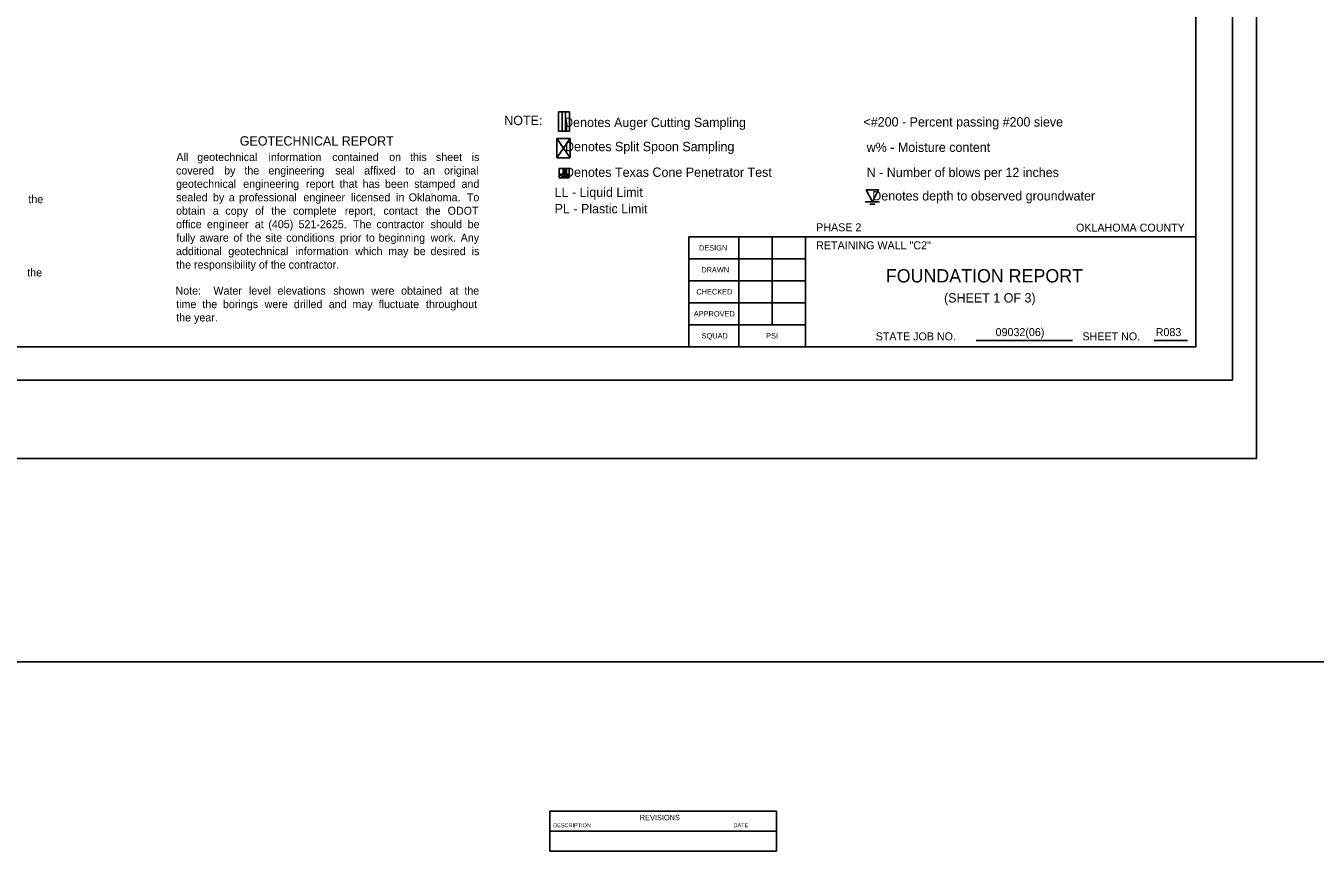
# Model space of a CAD drawing. Extents: x -2 to 138, y 24 to 58.
# Drawn here: x 24.17 to 43.5, y 24.08 to 36.46 of the extents above; entities that cross this region are included whole.
import ezdxf

# ---------------------------------------------------------------- set-up
doc = ezdxf.new("R2010")
doc.units = 0
for name, color, linetype in [('4', 7, 'Continuous'), ('REVBLK', 7, 'Continuous'), ('S', 7, 'Continuous'), ('SHT_Plot_Shape_Full', 7, 'Continuous'), ('SHT_Plot_Shape_Half', 7, 'Continuous'), ('SHT_Sheet_Border', 7, 'Continuous'), ('SHT_Standard_Sheet_Lines', 7, 'Continuous'), ('SHT_Standard_Sheet_Txt', 7, 'Continuous'), ('T', 7, 'Continuous'), ('T-5', 7, 'Continuous'), ('Text', 7, 'Continuous')]:
    doc.layers.add(name, color=color, linetype=linetype)

# ---------------------------------------------------------------- blocks, each defined once
blk = doc.blocks.new('DGRFC_WTLEV1_1')
for points in [[(-0.005, 0), (0.005, 0)], [(0, 0), (0.00417, 0.00833), (-0.00417, 0.00833), (0, 0)], [(-0.00167, -0.00167), (0.00167, -0.00167)]]:
    blk.add_lwpolyline(points)

msp = doc.modelspace()

# ---------------------------------------------------------------- linework, layer by layer
msp.add_line((32.155, 35.172), (32.155, 34.881))
for points in [[(32.155, 35.172), (32.322, 35.172)], [(32.322, 34.881), (32.322, 35.172)], [(32.155, 34.881), (32.322, 34.881)], [(32.155, 34.881), (32.322, 34.881)]]:
    msp.add_lwpolyline(points)
for points in [[(32.213, 35.172), (32.213, 34.881), (32.263, 34.881), (32.263, 35.172)], [(32.278, 35.005), (32.272, 35.047), (32.263, 35.087), (32.278, 35.005)], [(32.263, 35.087), (32.263, 34.881), (32.278, 35.005), (32.263, 35.087)], [(32.263, 34.881), (32.278, 34.922), (32.278, 35.005), (32.263, 34.881)], [(32.278, 34.922), (32.28, 34.963), (32.278, 35.005), (32.278, 34.922)], [(32.263, 34.881), (32.272, 34.881), (32.278, 34.922), (32.263, 34.881)]]:
    msp.add_lwpolyline(points, close=True)
at = {"layer": 'REVBLK'}
for p, q in [((32.025, 24.676), (35.425, 24.676)), ((32.025, 24.676), (32.025, 24.076)), ((35.425, 24.676), (35.425, 24.076)), ((32.025, 24.376), (35.425, 24.376)), ((32.025, 24.076), (35.425, 24.076))]:
    msp.add_line(p, q, dxfattribs=at)
at = {"layer": 'S'}
msp.add_lwpolyline([(-2.212, 26.92), (137.529, 26.92), (137.529, 58.049), (-2.212, 58.049)], close=True, dxfattribs=at)
at = {"layer": 'SHT_Plot_Shape_Full'}
msp.add_lwpolyline([(6.624, 53.971), (42.624, 53.971), (42.624, 29.971), (6.624, 29.971)], close=True, dxfattribs=at)
at = {"layer": 'SHT_Plot_Shape_Half'}
msp.add_lwpolyline([(8.262, 53.146), (42.262, 53.146), (42.262, 31.146), (8.262, 31.146)], close=True, dxfattribs=at)
at = {"layer": 'SHT_Sheet_Border'}
for p, q in [((34.112, 31.646), (34.112, 33.296)), ((34.112, 33.296), (41.712, 33.296)), ((35.862, 31.646), (35.862, 33.297))]:
    msp.add_line(p, q, dxfattribs=at)
msp.add_lwpolyline([(10.212, 52.646), (41.712, 52.646), (41.712, 31.646), (10.212, 31.646)], close=True, dxfattribs=at)
at = {"layer": 'SHT_Standard_Sheet_Lines'}
for p, q in [((34.862, 31.646), (34.862, 33.297)), ((35.362, 31.976), (35.362, 33.297)), ((38.422, 31.742), (39.863, 31.742)), ((41.087, 31.742), (41.59, 31.742))]:
    msp.add_line(p, q, dxfattribs=at)
for points in [[(35.862, 32.966), (34.112, 32.966)], [(35.862, 32.636), (34.112, 32.636)], [(35.862, 32.306), (34.112, 32.306)], [(35.862, 31.976), (34.112, 31.976)]]:
    msp.add_lwpolyline(points, dxfattribs=at)
at = {"layer": 'Text'}
for p, q in [((32.131, 34.481), (32.131, 34.773)), ((32.167, 34.181), (32.167, 34.322))]:
    msp.add_line(p, q, dxfattribs=at)
for points in [[(32.131, 34.481), (32.331, 34.773)], [(32.131, 34.773), (32.331, 34.481)], [(32.131, 34.773), (32.331, 34.773)], [(32.331, 34.481), (32.331, 34.773)], [(32.131, 34.481), (32.331, 34.481)], [(32.167, 34.322), (32.317, 34.322)], [(32.317, 34.181), (32.317, 34.322)], [(32.167, 34.181), (32.317, 34.181)]]:
    msp.add_lwpolyline(points, dxfattribs=at)
for points in [[(32.227, 34.237), (32.167, 34.237), (32.242, 34.181), (32.227, 34.237)], [(32.227, 34.237), (32.257, 34.322), (32.227, 34.322), (32.227, 34.237)], [(32.227, 34.237), (32.257, 34.237), (32.257, 34.322), (32.227, 34.237)], [(32.227, 34.237), (32.242, 34.181), (32.257, 34.237), (32.227, 34.237)], [(32.242, 34.181), (32.317, 34.237), (32.257, 34.237), (32.242, 34.181)]]:
    msp.add_lwpolyline(points, close=True, dxfattribs=at)

# ---------------------------------------------------------------- block references
at = {"layer": 'Text', "xscale": 21.6, "yscale": 21.6}
msp.add_blockref('DGRFC_WTLEV1_1', (36.863, 33.823), dxfattribs=at)

# ---------------------------------------------------------------- texts
at = {"layer": '4'}
msp.add_text('FOUNDATION REPORT', height=0.2, dxfattribs=at).set_placement((37.065, 32.611))
at = {"layer": 'REVBLK'}
for s, height, p in [('REVISIONS', 0.08, (33.376, 24.542)), ('DESCRIPTION', 0.06, (32.077, 24.436)), ('DATE', 0.06, (34.781, 24.436))]:
    msp.add_text(s, height=height, dxfattribs=at).set_placement(p)
at = {"layer": 'SHT_Standard_Sheet_Txt'}
for s, height, p in [('DESIGN', 0.08, (34.264, 33.091)), ('DRAWN', 0.08, (34.299, 32.761)), ('CHECKED', 0.08, (34.225, 32.431)), ('APPROVED', 0.08, (34.186, 32.101)), ('SQUAD', 0.08, (34.303, 31.771)), ('PSI', 0.08, (35.27, 31.771)), ('STATE JOB NO.', 0.12, (36.913, 31.742)), ('SHEET NO. ', 0.12, (40.013, 31.742))]:
    msp.add_text(s, height=height, dxfattribs=at).set_placement(p)
at = {"layer": 'T'}
for s, p in [('PHASE 2', (36.021, 33.379)), ('OKLAHOMA COUNTY', (39.917, 33.374)), ('RETAINING WALL "C2" ', (36.021, 33.108)), ('09032(06)', (38.711, 31.806)), ('R083', (41.112, 31.806))]:
    msp.add_text(s, height=0.12, dxfattribs=at).set_placement(p)
at = {"layer": 'T-5'}
msp.add_text('(SHEET 1 OF 3)', height=0.14, dxfattribs=at).set_placement((37.938, 32.31))
at = {"layer": 'Text'}
for s, height, p in [('NOTE:', 0.14, (31.344, 34.972)), ('    Denotes Auger Cutting Sampling', 0.14, (32.033, 34.943)), (' <#200 - Percent passing #200 sieve', 0.14, (36.678, 34.951)), ('GEOTECHNICAL REPORT', 0.14, (27.378, 34.665)), ('    Denotes Split Spoon Sampling', 0.14, (32.047, 34.581)), ('w% - Moisture content', 0.14, (36.778, 34.57)), ('All', 0.12, (26.428, 34.433)), ('geotechnical', 0.12, (26.741, 34.433)), ('information', 0.12, (27.809, 34.433)), ('contained', 0.12, (28.765, 34.433)), ('on', 0.12, (29.618, 34.433)), ('this', 0.12, (29.931, 34.433)), ('sheet', 0.12, (30.319, 34.433)), ('is ', 0.12, (30.855, 34.433)), ('covered', 0.12, (26.422, 34.231)), ('by', 0.12, (27.144, 34.231)), ('the', 0.12, (27.447, 34.231)), ('engineering', 0.12, (27.807, 34.231)), ('seal', 0.12, (28.809, 34.231)), ('affixed', 0.12, (29.243, 34.231)), ('to', 0.12, (29.863, 34.231)), ('an', 0.12, (30.129, 34.231)), ('original ', 0.12, (30.441, 34.231)), ('    Denotes Texas Cone Penetrator Test', 0.14, (32.047, 34.196)), ('N - Number of blows per 12 inches', 0.14, (36.778, 34.193)), ('geotechnical', 0.12, (26.423, 34.031)), ('engineering', 0.12, (27.43, 34.031)), ('report', 0.12, (28.371, 34.031)), ('that', 0.12, (28.875, 34.031)), ('has', 0.12, (29.22, 34.031)), ('been', 0.12, (29.556, 34.031)), ('stamped', 0.12, (29.994, 34.031)), ('and ', 0.12, (30.703, 34.031)), (' LL - Liquid Limit', 0.14, (32.047, 33.895)), ('the ', 0.12, (24.209, 33.801)), ('sealed', 0.12, (26.423, 33.829)), ('by', 0.12, (26.977, 33.829)), ('a', 0.12, (27.214, 33.829)), ('professional', 0.12, (27.368, 33.829)), ('engineer', 0.12, (28.332, 33.829)), ('licensed', 0.12, (29.047, 33.829)), ('in', 0.12, (29.722, 33.829)), ('Oklahoma.', 0.12, (29.912, 33.829)), ('To ', 0.12, (30.783, 33.829)), ('    Denotes depth to observed groundwater', 0.14, (36.654, 33.841)), ('obtain', 0.12, (26.423, 33.627)), ('a', 0.12, (26.974, 33.627)), ('copy', 0.12, (27.162, 33.627)), ('of', 0.12, (27.61, 33.627)), ('the', 0.12, (27.851, 33.627)), ('complete', 0.12, (28.178, 33.627)), ('report,', 0.12, (28.953, 33.627)), ('contact', 0.12, (29.532, 33.627)), ('the', 0.12, (30.167, 33.627)), ('ODOT ', 0.12, (30.495, 33.627)), (' PL - Plastic Limit', 0.14, (32.047, 33.648)), ('office', 0.12, (26.423, 33.425)), ('engineer', 0.12, (26.886, 33.425)), ('at', 0.12, (27.603, 33.425)), ('(405)', 0.12, (27.806, 33.425)), ('521-2625.', 0.12, (28.259, 33.425)), ('The', 0.12, (29.077, 33.425)), ('contractor', 0.12, (29.428, 33.425)), ('should', 0.12, (30.239, 33.425)), ('be ', 0.12, (30.795, 33.425)), ('fully', 0.12, (26.427, 33.223)), ('aware', 0.12, (26.776, 33.223)), ('of', 0.12, (27.283, 33.223)), ('the', 0.12, (27.48, 33.223)), ('site', 0.12, (27.764, 33.223)), ('conditions', 0.12, (28.076, 33.223)), ('prior', 0.12, (28.882, 33.223)), ('to', 0.12, (29.27, 33.223)), ('beginning', 0.12, (29.461, 33.223)), ('work.', 0.12, (30.239, 33.223)), ('Any ', 0.12, (30.691, 33.223)), ('additional', 0.12, (26.422, 33.021)), ('geotechnical', 0.12, (27.206, 33.021)), ('information', 0.12, (28.214, 33.021)), ('which', 0.12, (29.109, 33.021)), ('may', 0.12, (29.604, 33.021)), ('be', 0.12, (29.987, 33.021)), ('desired', 0.12, (30.239, 33.021)), ('is ', 0.12, (30.855, 33.021)), ('the responsibility of the contractor.', 0.12, (26.425, 32.819)), ('the ', 0.12, (24.191, 32.701)), ('Note:', 0.12, (26.415, 32.428)), ('Water', 0.12, (26.983, 32.428)), ('level', 0.12, (27.516, 32.428)), ('elevations', 0.12, (27.944, 32.428)), ('shown', 0.12, (28.782, 32.428)), ('were', 0.12, (29.35, 32.428)), ('obtained', 0.12, (29.797, 32.428)), ('at', 0.12, (30.523, 32.428)), ('the ', 0.12, (30.746, 32.428)), ('time', 0.12, (26.425, 32.226)), ('the', 0.12, (26.817, 32.226)), ('borings', 0.12, (27.126, 32.226)), ('were', 0.12, (27.751, 32.226)), ('drilled', 0.12, (28.19, 32.226)), ('and', 0.12, (28.713, 32.226)), ('may', 0.12, (29.068, 32.226)), ('fluctuate', 0.12, (29.46, 32.226)), ('throughout ', 0.12, (30.17, 32.226)), ('the year.', 0.12, (26.425, 32.026))]:
    msp.add_text(s, height=height, dxfattribs=at).set_placement(p)

doc.saveas('drawing.dxf')
